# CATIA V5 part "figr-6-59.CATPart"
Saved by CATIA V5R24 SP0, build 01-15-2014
Part number: Part1
Bounding box of the stored display mesh (mm): x -50.648 to 73.742, y -72.183 to 95.277, z -40 to 40
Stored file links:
  D:\KAVITA\CATIA V5-6R2014 Project_ Kavita\CATIA V5-6R2014_partfiles\Partfiles\c06_catia_v5-6r2014_prt\figr-6-59.CATPart
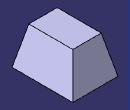
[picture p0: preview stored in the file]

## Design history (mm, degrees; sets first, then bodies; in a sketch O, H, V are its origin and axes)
Body1 (main body)
  Sketch1 on xy-plane, origin (0, 0, 0), H (1, 0, 0), V (0, 1, 0)
    line L1 (-50.6478, 72.1832) -> (50.6478, 72.1832)
    line L2 (50.6478, 72.1832) -> (50.6478, -72.1832)
    line L3 (50.6478, -72.1832) -> (-50.6478, -72.1832)
    line L4 (-50.6478, -72.1832) -> (-50.6478, 72.1832)
    axis line L5 (50.6478, -72.1832) -> (-50.6478, 72.1832)
    horizontal: L1 H, L3 H
    vertical: L2 V, L4 V
    midpoint: O L5
  Pad1: profile Sketch1, direction (0, 0, 1), length 40, mirrored extent
  Draft1: Angle 30, Neutral xy-plane, PullDir (0, 0, 1), SupportToDraft (face of Pad1; face of Pad1)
